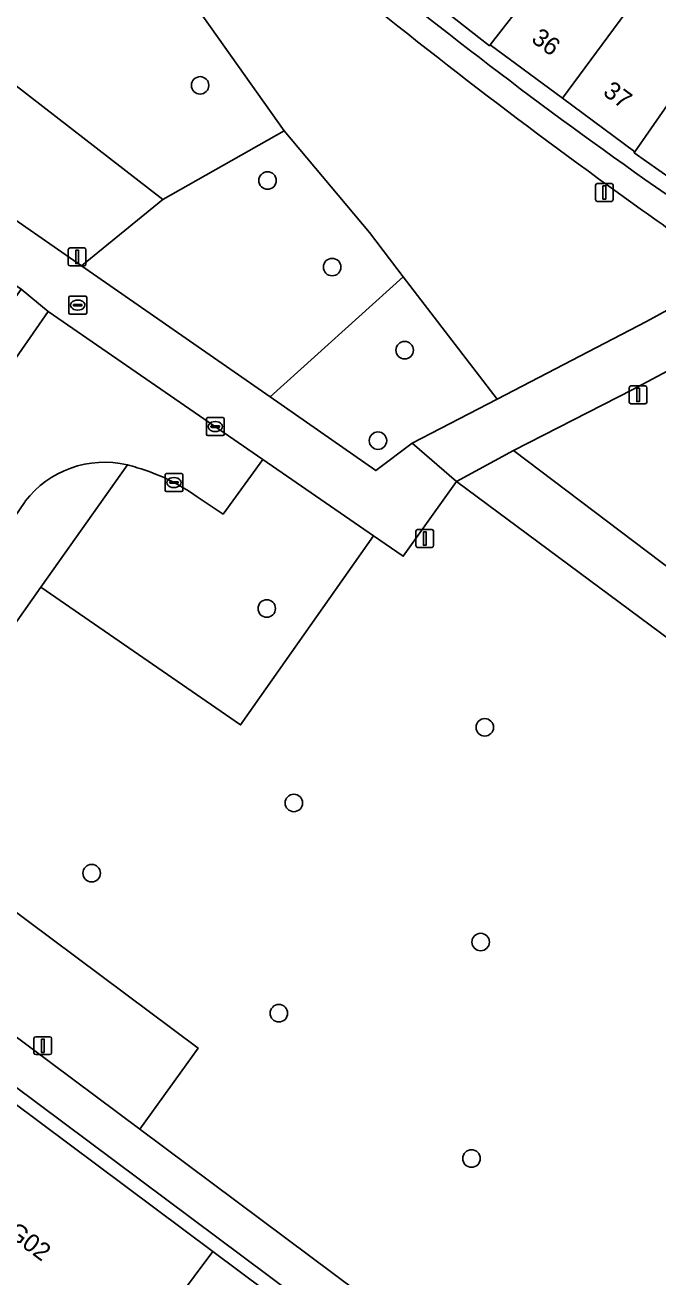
# Model space of a CAD drawing. Extents: x 160023 to 161302, y 384750 to 385707.
# Drawn here: x 160333.6 to 160369, y 385301.3 to 385371.2 of the extents above; entities that cross this region are included whole.
import ezdxf

# ---------------------------------------------------------------- set-up
doc = ezdxf.new("R2010")
doc.units = 0
for name, color, linetype in [('IMGEO_Boom', 7, 'Continuous'), ('IMGEO_Grasland_overig', 7, 'Continuous'), ('IMGEO_Groenvoorziening', 7, 'Continuous'), ('IMGEO_Kolk', 7, 'Continuous'), ('IMGEO_Lichtmast', 7, 'Continuous'), ('IMGEO_Pand', 7, 'Continuous'), ('IMGEO_Pand_nummerreeks', 7, 'Continuous'), ('IMGEO_Rijbaan_lokaal_open', 7, 'Continuous'), ('IMGEO_Rioolput', 7, 'Continuous'), ('IMGEO_Voetpad_open', 7, 'Continuous')]:
    doc.layers.add(name, color=color, linetype=linetype)

msp = doc.modelspace()

# ---------------------------------------------------------------- linework, layer by layer
at = {"layer": 'IMGEO_Boom'}
for centre in [(160343.35, 385367.865), (160347.124, 385362.547), (160350.739, 385357.708), (160354.797, 385353.06), (160353.3, 385348.005), (160347.08, 385338.621), (160359.277, 385331.975), (160348.596, 385327.751), (160337.282, 385323.823), (160359.046, 385319.973), (160347.757, 385315.994), (160358.534, 385307.871)]:
    msp.add_circle(centre, 0.489, dxfattribs=at)
at = {"layer": 'IMGEO_Grasland_overig'}
msp.add_lwpolyline([(160372.006, 385353.223), (160367.551, 385350.863), (160360.892, 385347.448), (160375.119, 385336.693), (160440.214, 385288.427), (160451.586, 385285.854), (160464.832, 385276.029), (160469.141, 385272.846), (160469.269, 385273.017), (160471.586, 385276.117)], dxfattribs=at)
at = {"layer": 'IMGEO_Groenvoorziening'}
for points in [[(160371.194, 385360.55), (160371.27, 385360.497), (160371.772, 385361.193), (160367.631, 385364.097), (160367.668, 385364.149), (160363.619, 385367.146), (160359.582, 385370.133), (160359.54, 385370.08), (160355.775, 385373.037), (160355.813, 385373.085), (160351.947, 385376.273), (160348.113, 385379.435), (160344.373, 385382.742), (160340.616, 385386.063), (160340.569, 385386.012), (160337.065, 385389.267)], [(160335.532, 385387.443), (160329.427, 385378.337), (160332.682, 385377.332), (160337.094, 385376.363), (160341.324, 385374.825), (160348.057, 385365.324), (160352.819, 385359.632), (160354.717, 385357.159), (160359.962, 385350.324), (160368.323, 385354.67), (160373.187, 385357.328), (160370.563, 385359.142)], [(160353.056, 385342.687), (160346.853, 385346.948), (160344.637, 385343.9), (160343.195, 385344.864)], [(160325.57, 385327.213), (160334.44, 385339.82), (160339.283, 385346.647)], [(160339.283, 385346.647), (160334.44, 385339.82), (160345.613, 385332.114), (160353.056, 385342.687)], [(160333.555, 385344.612), (160319.859, 385324.51), (160321.516, 385323.274), (160339.974, 385309.507), (160343.235, 385314.042), (160325.57, 385327.213)]]:
    msp.add_lwpolyline(points, dxfattribs=at)
for points in [[(160329.427, 385378.337), (160326.036, 385373.28), (160326.164, 385373.185), (160341.261, 385361.489), (160348.057, 385365.324), (160341.324, 385374.825), (160337.094, 385376.363), (160332.682, 385377.332)], [(160326.164, 385373.185), (160322.531, 385367.621), (160336.709, 385357.777), (160341.261, 385361.489)], [(160354.717, 385357.159), (160352.819, 385359.632), (160348.057, 385365.324), (160341.261, 385361.489), (160336.709, 385357.777), (160347.267, 385350.446)], [(160354.717, 385357.159), (160347.267, 385350.446), (160350.714, 385348.053), (160353.189, 385346.335), (160355.211, 385347.855), (160359.962, 385350.324)], [(160357.697, 385345.725), (160354.718, 385341.545), (160353.056, 385342.687), (160345.613, 385332.114), (160334.44, 385339.82), (160325.57, 385327.213), (160343.235, 385314.042), (160339.974, 385309.507), (160394.21, 385269.049), (160405.856, 385284.994), (160415.293, 385297.914), (160400.011, 385309.258), (160402.452, 385312.526), (160390.707, 385321.238), (160390.121, 385320.417), (160384.461, 385324.633), (160385.071, 385325.42)]]:
    msp.add_lwpolyline(points, close=True, dxfattribs=at)
for centre, radius, start, end in [((160531.978, 385594.918), 284.218, 226.27072, 235.54857), ((160552.567, 385620.207), 318.243, 230.0934, 234.15663), ((160549.312, 385615.386), 312.43, 234.12285, 235.10138), ((160337.998, 385341.185), 5.611, 76.7638, 142.35364), ((160337.89, 385340.823), 5.989, 71.08946, 76.55079), ((160336.703, 385335.712), 11.221, 54.64884, 73.81251)]:
    msp.add_arc(centre, radius, start, end, dxfattribs=at)
at = {"layer": 'IMGEO_Kolk'}
for p, q in [((160343.7, 385348.365), (160343.7, 385349.217)), ((160343.775, 385349.291), (160344.627, 385349.291)), ((160344.188, 385349.071), (160344.213, 385349.071)), ((160344.701, 385349.217), (160344.701, 385348.365)), ((160343.959, 385348.785), (160343.959, 385348.797)), ((160344.397, 385348.748), (160343.999, 385348.748)), ((160344.002, 385348.834), (160344.4, 385348.834)), ((160344.211, 385348.511), (160344.186, 385348.511)), ((160344.443, 385348.797), (160344.443, 385348.785)), ((160344.627, 385348.291), (160343.775, 385348.291)), ((160341.387, 385345.236), (160341.387, 385346.088)), ((160341.462, 385346.162), (160342.314, 385346.162)), ((160341.646, 385345.656), (160341.646, 385345.668)), ((160342.084, 385345.619), (160341.686, 385345.619)), ((160341.689, 385345.705), (160342.087, 385345.705)), ((160341.875, 385345.942), (160341.9, 385345.942)), ((160342.13, 385345.668), (160342.13, 385345.656)), ((160342.388, 385346.088), (160342.388, 385345.236)), ((160342.314, 385345.162), (160341.462, 385345.162)), ((160341.898, 385345.382), (160341.873, 385345.382))]:
    msp.add_line(p, q, dxfattribs=at)
for points in [[(160343.7, 385348.365), (160343.7, 385349.217)], [(160343.775, 385349.291), (160344.627, 385349.291)], [(160344.701, 385349.217), (160344.701, 385348.365)], [(160344.627, 385348.291), (160343.775, 385348.291)], [(160341.387, 385345.236), (160341.387, 385346.088)], [(160341.462, 385346.162), (160342.314, 385346.162)], [(160342.388, 385346.088), (160342.388, 385345.236)], [(160342.314, 385345.162), (160341.462, 385345.162)]]:
    msp.add_lwpolyline(points, dxfattribs=at)
for centre, radius, start, end in [((160343.777, 385349.215), 0.0765, 91.55205, 178.44795), ((160343.777, 385349.215), 0.0765, 91.55205, 178.44795), ((160344.625, 385349.215), 0.0765, 1.55205, 88.44795), ((160344.625, 385349.215), 0.0765, 1.55205, 88.44795), ((160343.777, 385348.367), 0.0765, 181.55205, 268.44795), ((160343.777, 385348.367), 0.0765, 181.55205, 268.44795), ((160343.999, 385348.794), 0.0403, 85.87752, 175.75265), ((160343.996, 385348.784), 0.0366, 178.93798, 274.71019), ((160344.4, 385348.791), 0.043, 264.86636, 352.45326), ((160344.404, 385348.796), 0.0386, 1.73085, 96.63898), ((160344.625, 385348.367), 0.0765, 271.55205, 358.44795), ((160344.625, 385348.367), 0.0765, 271.55205, 358.44795), ((160341.464, 385346.086), 0.0765, 91.55205, 178.44795), ((160341.464, 385346.086), 0.0765, 91.55205, 178.44795), ((160341.686, 385345.665), 0.0403, 85.87752, 175.75265), ((160341.683, 385345.655), 0.0366, 178.93798, 274.71019), ((160342.087, 385345.662), 0.043, 264.86636, 352.45326), ((160342.091, 385345.667), 0.0386, 1.73085, 96.63898), ((160342.312, 385346.086), 0.0765, 1.55205, 88.44795), ((160342.312, 385346.086), 0.0765, 1.55205, 88.44795), ((160341.464, 385345.238), 0.0765, 181.55205, 268.44795), ((160341.464, 385345.238), 0.0765, 181.55205, 268.44795), ((160342.312, 385345.238), 0.0765, 271.55205, 358.44795), ((160342.312, 385345.238), 0.0765, 271.55205, 358.44795)]:
    msp.add_arc(centre, radius, start, end, dxfattribs=at)
for centre, major_axis, ratio, start_param, end_param in [((160344.187, 385348.791), (-0.387, 0.002), 0.722429, 4.712389, 7.853982), ((160344.212, 385348.791), (-0.39, 0.002), 0.717154, 1.570796, 4.712389), ((160341.874, 385345.662), (-0.387, 0.002), 0.722429, 4.712389, 7.853982), ((160341.899, 385345.662), (-0.39, 0.002), 0.717154, 1.570796, 4.712389)]:
    msp.add_ellipse(centre, major_axis=major_axis, ratio=ratio, start_param=start_param, end_param=end_param, dxfattribs=at)
at = {"layer": 'IMGEO_Lichtmast'}
for p, q in [((160365.571, 385362.38), (160366.361, 385362.38)), ((160366.361, 385362.38), (160365.571, 385362.38)), ((160365.471, 385361.48), (160365.471, 385362.28)), ((160365.471, 385362.28), (160365.471, 385361.48)), ((160366.461, 385362.28), (160366.461, 385361.48)), ((160366.461, 385361.48), (160366.461, 385362.28)), ((160366.361, 385361.38), (160365.571, 385361.38)), ((160365.571, 385361.38), (160366.361, 385361.38)), ((160335.975, 385357.876), (160335.975, 385358.676)), ((160335.975, 385358.676), (160335.975, 385357.876)), ((160336.075, 385358.776), (160336.865, 385358.776)), ((160336.865, 385358.776), (160336.075, 385358.776)), ((160336.965, 385358.676), (160336.965, 385357.876)), ((160336.965, 385357.876), (160336.965, 385358.676)), ((160336.865, 385357.776), (160336.075, 385357.776)), ((160336.075, 385357.776), (160336.865, 385357.776)), ((160367.357, 385350.163), (160367.357, 385350.963)), ((160367.357, 385350.963), (160367.357, 385350.163)), ((160367.457, 385351.063), (160368.247, 385351.063)), ((160368.247, 385351.063), (160367.457, 385351.063)), ((160368.347, 385350.963), (160368.347, 385350.163)), ((160368.347, 385350.163), (160368.347, 385350.963)), ((160368.247, 385350.063), (160367.457, 385350.063)), ((160367.457, 385350.063), (160368.247, 385350.063)), ((160355.42, 385342.135), (160355.42, 385342.935)), ((160355.42, 385342.935), (160355.42, 385342.135)), ((160355.52, 385343.035), (160356.31, 385343.035)), ((160356.31, 385343.035), (160355.52, 385343.035)), ((160356.41, 385342.935), (160356.41, 385342.135)), ((160356.41, 385342.135), (160356.41, 385342.935)), ((160356.31, 385342.035), (160355.52, 385342.035)), ((160355.52, 385342.035), (160356.31, 385342.035)), ((160334.054, 385313.778), (160334.054, 385314.578)), ((160334.054, 385314.578), (160334.054, 385313.778)), ((160334.154, 385314.678), (160334.944, 385314.678)), ((160334.944, 385314.678), (160334.154, 385314.678)), ((160335.044, 385314.578), (160335.044, 385313.778)), ((160335.044, 385313.778), (160335.044, 385314.578)), ((160334.944, 385313.678), (160334.154, 385313.678)), ((160334.154, 385313.678), (160334.944, 385313.678))]:
    msp.add_line(p, q, dxfattribs=at)
for points in [[(160365.891, 385362.255), (160366.041, 385362.255), (160366.041, 385361.505), (160365.891, 385361.505), (160365.891, 385362.255)], [(160336.395, 385358.651), (160336.545, 385358.651), (160336.545, 385357.901), (160336.395, 385357.901), (160336.395, 385358.651)], [(160367.777, 385350.938), (160367.927, 385350.938), (160367.927, 385350.188), (160367.777, 385350.188), (160367.777, 385350.938)], [(160355.84, 385342.91), (160355.99, 385342.91), (160355.99, 385342.16), (160355.84, 385342.16), (160355.84, 385342.91)], [(160334.474, 385314.553), (160334.624, 385314.553), (160334.624, 385313.803), (160334.474, 385313.803), (160334.474, 385314.553)]]:
    msp.add_lwpolyline(points, dxfattribs=at)
for centre, start, end in [((160365.571, 385362.28), 90, 180), ((160365.571, 385362.28), 90, 180), ((160366.361, 385362.28), 0, 90), ((160366.361, 385362.28), 360, 90), ((160365.571, 385361.48), 180, 270), ((160365.571, 385361.48), 180, 270), ((160366.361, 385361.48), 270, 0), ((160366.361, 385361.48), 270, 0), ((160336.075, 385358.676), 90, 180), ((160336.075, 385358.676), 90, 180), ((160336.865, 385358.676), 0, 90), ((160336.865, 385358.676), 360, 90), ((160336.075, 385357.876), 180, 270), ((160336.075, 385357.876), 180, 270), ((160336.865, 385357.876), 270, 0), ((160336.865, 385357.876), 270, 0), ((160367.457, 385350.963), 90, 180), ((160367.457, 385350.963), 90, 180), ((160368.247, 385350.963), 0, 90), ((160368.247, 385350.963), 360, 90), ((160367.457, 385350.163), 180, 270), ((160367.457, 385350.163), 180, 270), ((160368.247, 385350.163), 270, 0), ((160368.247, 385350.163), 270, 0), ((160355.52, 385342.935), 90, 180), ((160355.52, 385342.935), 90, 180), ((160356.31, 385342.935), 0, 90), ((160356.31, 385342.935), 360, 90), ((160355.52, 385342.135), 180, 270), ((160355.52, 385342.135), 180, 270), ((160356.31, 385342.135), 270, 0), ((160356.31, 385342.135), 270, 0), ((160334.154, 385314.578), 90, 180), ((160334.154, 385314.578), 90, 180), ((160334.944, 385314.578), 0, 90), ((160334.944, 385314.578), 360, 90), ((160334.154, 385313.778), 180, 270), ((160334.154, 385313.778), 180, 270), ((160334.944, 385313.778), 270, 0), ((160334.944, 385313.778), 270, 0)]:
    msp.add_arc(centre, 0.1, start, end, dxfattribs=at)
at = {"layer": 'IMGEO_Pand'}
for points in [[(160365.214, 385377.355), (160364.991, 385377.526), (160361.429, 385380.271), (160355.813, 385373.085), (160355.775, 385373.037), (160359.54, 385370.08), (160359.582, 385370.133)], [(160369.699, 385375.388), (160365.672, 385378.409), (160364.991, 385377.526), (160365.214, 385377.355), (160359.582, 385370.133), (160363.619, 385367.146)], [(160373.551, 385372.589), (160369.699, 385375.388), (160363.619, 385367.146), (160367.668, 385364.149)], [(160377.696, 385369.674), (160373.551, 385372.589), (160367.668, 385364.149), (160367.631, 385364.097), (160371.772, 385361.193)], [(160329.511, 385313.511), (160329.975, 385314.134), (160329.671, 385314.36), (160325.396, 385308.625), (160323.007, 385305.421), (160323.271, 385305.224), (160323.86, 385306.015), (160324.276, 385306.573), (160330.397, 385302.01), (160332.629, 385300.346), (160335.219, 385298.415), (160338.754, 385295.78), (160338.342, 385295.227), (160337.752, 385294.436), (160337.856, 385294.359), (160344.055, 385302.669)], [(160358.796, 385291.679), (160344.055, 385302.669), (160337.856, 385294.359), (160337.96, 385294.281), (160338.543, 385295.063), (160338.969, 385295.634), (160342.606, 385292.923), (160345.176, 385291.006), (160347.248, 385289.462), (160347.481, 385289.288), (160353.426, 385284.856), (160352.984, 385284.263), (160352.387, 385283.462), (160352.567, 385283.328)]]:
    msp.add_lwpolyline(points, close=True, dxfattribs=at)
at = {"layer": 'IMGEO_Rijbaan_lokaal_open'}
for points in [[(160343.195, 385344.864), (160344.637, 385343.9), (160346.853, 385346.948), (160334.85, 385355.222), (160304.94, 385312.099)], [(160318.625, 385322.728), (160319.859, 385324.51), (160333.555, 385344.612)]]:
    msp.add_lwpolyline(points, dxfattribs=at)
for centre, radius, start, end in [((160337.998, 385341.185), 5.611, 76.7638, 142.35364), ((160337.89, 385340.823), 5.989, 71.08946, 76.55079), ((160336.703, 385335.712), 11.221, 54.64884, 73.81251)]:
    msp.add_arc(centre, radius, start, end, dxfattribs=at)
at = {"layer": 'IMGEO_Rioolput'}
for p, q in [((160336.003, 385355.155), (160336.003, 385356.007)), ((160336.078, 385356.081), (160336.93, 385356.081)), ((160337.004, 385356.007), (160337.004, 385355.155)), ((160336.262, 385355.575), (160336.262, 385355.587)), ((160336.7, 385355.538), (160336.302, 385355.538)), ((160336.305, 385355.624), (160336.703, 385355.624)), ((160336.514, 385355.301), (160336.489, 385355.301)), ((160336.491, 385355.861), (160336.516, 385355.861)), ((160336.746, 385355.587), (160336.746, 385355.575)), ((160336.93, 385355.081), (160336.078, 385355.081))]:
    msp.add_line(p, q, dxfattribs=at)
for points in [[(160336.003, 385355.155), (160336.003, 385356.007)], [(160336.078, 385356.081), (160336.93, 385356.081)], [(160337.004, 385356.007), (160337.004, 385355.155)], [(160336.93, 385355.081), (160336.078, 385355.081)]]:
    msp.add_lwpolyline(points, dxfattribs=at)
for centre, radius, start, end in [((160336.08, 385356.005), 0.0765, 91.55205, 178.44795), ((160336.08, 385356.005), 0.0765, 91.55205, 178.44795), ((160336.928, 385356.005), 0.0765, 1.55205, 88.44795), ((160336.928, 385356.005), 0.0765, 1.55205, 88.44795), ((160336.302, 385355.584), 0.0403, 85.87752, 175.75265), ((160336.299, 385355.574), 0.0366, 178.93798, 274.71019), ((160336.703, 385355.581), 0.043, 264.86636, 352.45326), ((160336.707, 385355.586), 0.0386, 1.73085, 96.63898), ((160336.08, 385355.157), 0.0765, 181.55205, 268.44795), ((160336.08, 385355.157), 0.0765, 181.55205, 268.44795), ((160336.928, 385355.157), 0.0765, 271.55205, 358.44795), ((160336.928, 385355.157), 0.0765, 271.55205, 358.44795)]:
    msp.add_arc(centre, radius, start, end, dxfattribs=at)
for centre, major_axis, ratio, start_param, end_param in [((160336.49, 385355.581), (-0.387, 0.002), 0.722429, 4.712389, 7.853982), ((160336.515, 385355.581), (-0.39, 0.002), 0.717154, 1.570796, 4.712389)]:
    msp.add_ellipse(centre, major_axis=major_axis, ratio=ratio, start_param=start_param, end_param=end_param, dxfattribs=at)
at = {"layer": 'IMGEO_Voetpad_open'}
for points in [[(160321.69, 385372.616), (160317.907, 385367.108), (160320.01, 385365.634), (160329.18, 385359.339), (160333.347, 385356.477), (160334.85, 385355.222), (160346.853, 385346.948), (160353.056, 385342.687), (160354.718, 385341.545), (160357.697, 385345.725), (160355.211, 385347.855), (160353.189, 385346.335), (160350.714, 385348.053), (160347.267, 385350.446), (160336.709, 385357.777), (160322.531, 385367.621), (160326.164, 385373.185)], [(160374.616, 385358.149), (160373.187, 385357.328), (160368.323, 385354.67), (160359.962, 385350.324), (160355.211, 385347.855), (160357.697, 385345.725), (160360.892, 385347.448), (160367.551, 385350.863), (160372.006, 385353.223)], [(160334.85, 385355.222), (160333.347, 385356.477), (160328.775, 385349.899), (160327.028, 385347.387), (160325.265, 385344.851), (160320.083, 385337.395), (160318.233, 385334.735), (160316.619, 385332.413), (160312.11, 385325.926), (160309.222, 385321.772), (160303.699, 385313.827)], [(160304.94, 385312.099), (160334.85, 385355.222)], [(160375.119, 385336.693), (160360.892, 385347.448), (160357.697, 385345.725), (160385.071, 385325.42)], [(160394.21, 385269.049), (160339.974, 385309.507), (160321.516, 385323.274), (160320.296, 385321.498), (160328.67, 385315.311), (160324.315, 385309.421), (160325.396, 385308.625), (160329.671, 385314.36), (160329.975, 385314.134), (160388.692, 385270.335)]]:
    msp.add_lwpolyline(points, dxfattribs=at)
msp.add_lwpolyline([(160358.796, 385291.679), (160373.594, 385280.647), (160388.24, 385269.728), (160388.692, 385270.335), (160329.975, 385314.134), (160329.511, 385313.511), (160344.055, 385302.669)], close=True, dxfattribs=at)
for centre, radius, start, end in [((160531.978, 385594.918), 284.218, 226.27072, 235.54857), ((160552.567, 385620.207), 318.243, 230.0934, 234.15663), ((160549.312, 385615.386), 312.43, 234.12285, 235.10138)]:
    msp.add_arc(centre, radius, start, end, dxfattribs=at)

# ---------------------------------------------------------------- texts
at = {"layer": 'IMGEO_Pand_nummerreeks'}
for s, rotation, p in [('36', 323.49686, (160361.821, 385370.343)), ('37', 323.49686, (160365.83, 385367.376)), ('98-108/G02', 323.29636, (160328.85, 385306.307))]:
    msp.add_text(s, height=1, rotation=rotation, dxfattribs=at).set_placement(p)

doc.saveas('drawing.dxf')
